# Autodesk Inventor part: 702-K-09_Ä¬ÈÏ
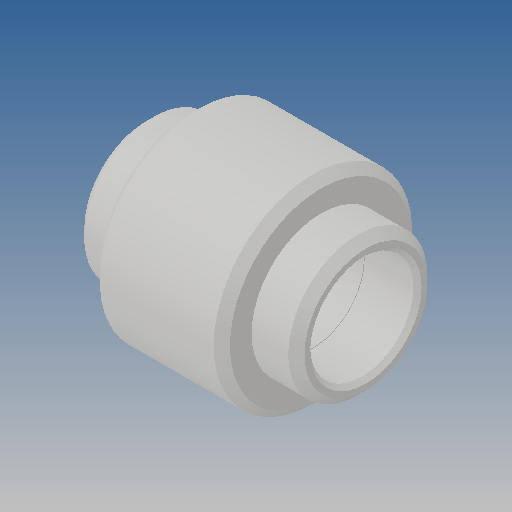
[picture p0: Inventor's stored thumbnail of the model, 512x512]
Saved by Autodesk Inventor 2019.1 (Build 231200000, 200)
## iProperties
Created: 2010-06
Part Number: 702-K-09_Ä¬ÈÏ
Material: Ogólny
Document SubType Name: Modeling
Designer: CADENGINEERING4
Density: 1 g/cm^3
Appearance: Domyślna
Author: CADENGINEERING4
Revision Number: ÈÎºÎ
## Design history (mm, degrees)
feature "NONE"
node "Bryła1"
